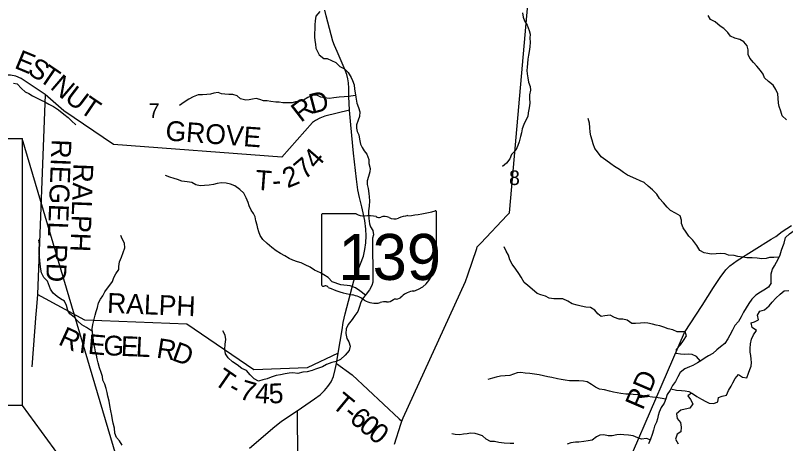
# Model space of a CAD drawing. Extents: x 0 to 34, y 0 to 22.
# Drawn here: x 4.921 to 7.127, y 17.503 to 18.731 of the extents above; entities that cross this region are included whole.
import ezdxf

# ---------------------------------------------------------------- set-up
doc = ezdxf.new("R2010")
doc.units = 0
for name, color, linetype in [('GM_X_County_Road', 7, 'Continuous'), ('GM_X_County_Road_Text', 7, 'Continuous'), ('GM_X_Minor_River', 7, 'Continuous'), ('GM_X_Section_Text', 7, 'Continuous'), ('GM_X_State_Location', 7, 'Continuous'), ('GM_X_State_Route', 7, 'Continuous'), ('GM_X_State_Shield', 7, 'Continuous'), ('GM_X_Township_Road', 7, 'Continuous'), ('GM_X_Township_Road_Text', 7, 'Continuous'), ('SH_Text', 7, 'Continuous')]:
    doc.layers.add(name, color=color, linetype=linetype)

msp = doc.modelspace()

# ---------------------------------------------------------------- linework, layer by layer
at = {"layer": 'GM_X_County_Road'}
msp.add_lwpolyline([(6.5942, 17.2578), (6.8375, 17.8217), (6.888, 17.8994), (6.9203, 17.9509), (6.9396, 17.9796), (6.9563, 18.001), (6.9677, 18.0129), (6.9885, 18.0281), (7.086, 18.0898), (7.0991, 18.0972), (7.1177, 18.1111), (7.1444, 18.1289)], dxfattribs=at)
at = {"layer": 'GM_X_Minor_River'}
for points in [[(5.7926, 18.7415), (5.7815, 18.7283), (5.7795, 18.7146), (5.7791, 18.7033), (5.779, 18.6904), (5.7781, 18.6805), (5.7781, 18.6691), (5.7791, 18.6585), (5.7802, 18.6486), (5.782, 18.6369), (5.7861, 18.6274), (5.791, 18.6178), (5.8041, 18.6071)], [(6.3738, 18.7376), (6.3756, 18.7258), (6.3789, 18.7152), (6.3868, 18.703), (6.3927, 18.6874), (6.3953, 18.6764), (6.3948, 18.665), (6.3959, 18.654), (6.395, 18.6407), (6.3927, 18.6267), (6.3911, 18.6169), (6.3891, 18.6055), (6.3875, 18.5926), (6.3867, 18.5824), (6.3855, 18.5729), (6.3866, 18.5634), (6.3891, 18.5513), (6.3906, 18.5391), (6.3954, 18.5266), (6.3965, 18.5163), (6.3937, 18.5027), (6.394, 18.4932), (6.3943, 18.4792), (6.3923, 18.4655), (6.39, 18.4511), (6.3884, 18.4409), (6.383, 18.4307), (6.3776, 18.4175), (6.373, 18.4057), (6.3703, 18.3936), (6.3679, 18.3834), (6.3637, 18.3686), (6.3602, 18.3576), (6.3541, 18.3448), (6.3422, 18.332), (6.3376, 18.3199), (6.3277, 18.3074), (6.3167, 18.298)], [(7.1296, 18.431), (7.1176, 18.4428), (7.1135, 18.4565), (7.1087, 18.4698), (7.1065, 18.4793), (7.1062, 18.4937), (7.1048, 18.5055), (7.0992, 18.5181), (7.0913, 18.531), (7.0785, 18.541), (7.0669, 18.5513), (7.0631, 18.5619), (7.0553, 18.573), (7.0448, 18.5852), (7.035, 18.5959), (7.0249, 18.6077), (7.0204, 18.6183), (7.0197, 18.6324), (7.0168, 18.643), (7.0074, 18.6552), (6.9961, 18.6614), (6.9821, 18.6649), (6.9697, 18.6714), (6.9618, 18.6817), (6.9498, 18.6928), (6.9396, 18.7), (6.9257, 18.7119), (6.9125, 18.7184), (6.9054, 18.7306)], [(5.8041, 18.6071), (5.814, 18.6067), (5.8264, 18.6013), (5.8392, 18.5959), (5.8505, 18.5841), (5.8633, 18.5772), (5.8746, 18.5665), (5.8829, 18.5531), (5.8866, 18.5436), (5.891, 18.5318), (5.8928, 18.5189), (5.8947, 18.5087), (5.8965, 18.4961), (5.899, 18.4794), (5.9035, 18.4665), (5.9072, 18.4544), (5.9063, 18.4411), (5.9032, 18.4301), (5.8978, 18.4173), (5.8978, 18.4074), (5.9, 18.3979), (5.9044, 18.3884), (5.9062, 18.3759), (5.9099, 18.3618), (5.914, 18.3519), (5.9204, 18.3424), (5.9279, 18.3325), (5.9331, 18.318), (5.9338, 18.3059), (5.9371, 18.2918), (5.9366, 18.2824), (5.9324, 18.2691), (5.9285, 18.2566), (5.9288, 18.2464), (5.9314, 18.235), (5.9332, 18.2202), (5.9346, 18.2107), (5.9353, 18.1989), (5.9344, 18.1838), (5.9325, 18.1705), (5.9324, 18.1603), (5.9335, 18.1485), (5.9349, 18.1337), (5.9382, 18.1242), (5.9449, 18.1139), (5.9468, 18.1021), (5.944, 18.0923), (5.944, 18.0805), (5.9435, 18.0711), (5.9435, 18.0616), (5.9437, 18.0479), (5.944, 18.0377), (5.9451, 18.0252), (5.9449, 17.999), (5.9445, 17.988), (5.9447, 17.9665)], [(4.9152, 18.5365), (4.9258, 18.5345), (4.9389, 18.5215), (4.9494, 18.5112), (4.9596, 18.507), (4.9702, 18.5004), (4.9811, 18.4939), (4.9947, 18.4874), (5.0056, 18.4828), (5.0166, 18.4766), (5.0301, 18.4693), (5.0448, 18.4601), (5.0599, 18.4471), (5.0723, 18.4376), (5.0817, 18.428), (5.0941, 18.4169)], [(5.8958, 18.5011), (5.8738, 18.4986), (5.8628, 18.4971), (5.8488, 18.4961), (5.8329, 18.4939), (5.8211, 18.4925), (5.8068, 18.4941), (5.7962, 18.4964), (5.7845, 18.5018), (5.772, 18.5015), (5.7587, 18.4952), (5.7462, 18.4873), (5.734, 18.484), (5.7234, 18.4825), (5.714, 18.4803), (5.7022, 18.4804), (5.6871, 18.4805), (5.6769, 18.4824), (5.6671, 18.4821), (5.6523, 18.4837), (5.6425, 18.4853), (5.6319, 18.4858), (5.6209, 18.49), (5.6104, 18.492), (5.6005, 18.4905), (5.5907, 18.4887), (5.5808, 18.4873), (5.5661, 18.4912), (5.5563, 18.5003), (5.5442, 18.5042), (5.5321, 18.5043), (5.5212, 18.5047), (5.5113, 18.5059), (5.5015, 18.5094), (5.4898, 18.5076), (5.4799, 18.505), (5.4697, 18.5039), (5.4572, 18.5029), (5.4443, 18.5026), (5.4303, 18.497), (5.4181, 18.491), (5.4044, 18.4816), (5.3915, 18.4726)], [(7.109, 18.0378), (7.0936, 18.0368), (7.0811, 18.0365), (7.0717, 18.0343), (7.0595, 18.0329), (7.0459, 18.0349), (7.0316, 18.0357), (7.0164, 18.0358), (7.0047, 18.0382), (6.99, 18.0398), (6.9794, 18.0421), (6.9635, 18.0434), (6.9537, 18.0469), (6.9404, 18.0481), (6.928, 18.0474), (6.9143, 18.0464), (6.9041, 18.0483), (6.8943, 18.0503), (6.8815, 18.0572), (6.8733, 18.0713), (6.8612, 18.0862), (6.8496, 18.098), (6.8421, 18.109), (6.8335, 18.1216), (6.8286, 18.1338), (6.8287, 18.144), (6.825, 18.1558), (6.8118, 18.1639), (6.7979, 18.1715), (6.7877, 18.1807), (6.7772, 18.1937), (6.7659, 18.2055), (6.7585, 18.2181), (6.7464, 18.2307), (6.7336, 18.241), (6.7216, 18.2513), (6.7107, 18.2567), (6.6986, 18.2621), (6.6748, 18.2725), (6.6624, 18.2805), (6.6511, 18.2893), (6.6375, 18.2978), (6.6262, 18.305), (6.6127, 18.3158), (6.5991, 18.3257), (6.5883, 18.3398), (6.5811, 18.3493), (6.5759, 18.3623), (6.573, 18.3733), (6.5693, 18.3855), (6.5671, 18.3961), (6.566, 18.409), (6.5654, 18.4219), (6.562, 18.4356)], [(5.8285, 17.9667), (5.8169, 17.979), (5.8045, 17.987), (5.7947, 17.9932), (5.7781, 18.0005), (5.7649, 18.0093), (5.7509, 18.0158), (5.7396, 18.0212), (5.7294, 18.0243), (5.7154, 18.0293), (5.7053, 18.034), (5.6932, 18.0413), (5.6804, 18.0485), (5.6679, 18.0558), (5.6551, 18.065), (5.6424, 18.0769), (5.6299, 18.0883), (5.6217, 18.1001), (5.6187, 18.1104), (5.6158, 18.1203), (5.6136, 18.1298), (5.6099, 18.1416), (5.6077, 18.153), (5.6028, 18.1625), (5.5961, 18.172), (5.5905, 18.1845), (5.5879, 18.1944), (5.5819, 18.2081), (5.5756, 18.2207), (5.5636, 18.2318), (5.5496, 18.2421), (5.5376, 18.2471), (5.5251, 18.2498), (5.5115, 18.2503), (5.4994, 18.2489), (5.4887, 18.2459), (5.4759, 18.2437), (5.4622, 18.2434), (5.4501, 18.2424), (5.438, 18.2455), (5.426, 18.2516), (5.4131, 18.254), (5.398, 18.2552), (5.3855, 18.2606), (5.3757, 18.2634), (5.3636, 18.2672), (5.3508, 18.2722)], [(7.0856, 17.9641), (7.0857, 17.9796), (7.0854, 17.9898), (7.0892, 18.0031), (7.095, 18.0129), (7.1015, 18.0235), (7.1072, 18.0337), (7.1118, 18.0447), (7.1153, 18.0579), (7.1192, 18.0685), (7.123, 18.0783), (7.1273, 18.0939), (7.1387, 18.1048), (7.152, 18.1138), (7.1638, 18.1198), (7.1767, 18.1227), (7.1873, 18.1177), (7.2005, 18.118), (7.2127, 18.1244), (7.2256, 18.1311), (7.2358, 18.1341), (7.2498, 18.1371)], [(5.1993, 17.9681), (5.2027, 17.9797), (5.2089, 17.9895), (5.2173, 18.002), (5.2173, 18.0114), (5.2193, 18.0239), (5.2247, 18.0379), (5.2297, 18.0512), (5.234, 18.0648), (5.2333, 18.0777), (5.227, 18.0903), (5.2229, 18.1001)], [(5.0134, 17.9691), (5.0028, 17.979), (4.9957, 17.993), (4.9935, 18.0037), (4.992, 18.0177), (4.9913, 18.0283), (4.9891, 18.0488), (4.9895, 18.062), (4.9896, 18.0753), (4.9885, 18.0878)], [(6.3787, 17.9656), (6.3697, 17.9806), (6.3626, 17.9909), (6.3544, 18.0038), (6.3435, 18.0179), (6.3372, 18.0305), (6.3338, 18.0434), (6.3271, 18.0552), (6.3211, 18.0674)], [(5.1419, 17.8248), (5.1245, 17.8364), (5.1117, 17.844), (5.0996, 17.8543), (5.089, 17.8657), (5.077, 17.8752), (5.0709, 17.8851), (5.0676, 17.8991), (5.0612, 17.9113), (5.0506, 17.9181), (5.0408, 17.925), (5.0295, 17.9349), (5.022, 17.9463), (5.0134, 17.9691)], [(5.2051, 17.548), (5.2014, 17.5616), (5.1992, 17.5719), (5.1973, 17.5836), (5.1943, 17.5977), (5.1918, 17.6125), (5.1895, 17.6254), (5.1862, 17.639), (5.1839, 17.6496), (5.1813, 17.6618), (5.1776, 17.6739), (5.1716, 17.6849), (5.1705, 17.6956), (5.1664, 17.7073), (5.1619, 17.7206), (5.1582, 17.7346), (5.1556, 17.7468), (5.1529, 17.757), (5.1507, 17.7665), (5.1481, 17.7775), (5.1459, 17.7885), (5.1448, 17.7988), (5.1441, 17.8082), (5.1422, 17.8215), (5.1411, 17.8321), (5.1427, 17.845), (5.1457, 17.8564), (5.1492, 17.8711), (5.1527, 17.8825), (5.1557, 17.8939), (5.1595, 17.9067), (5.1645, 17.917), (5.171, 17.9268), (5.1771, 17.9385), (5.1993, 17.9681)], [(5.9447, 17.9665), (5.9421, 17.9561), (5.9356, 17.9443), (5.9253, 17.9315), (5.9151, 17.9183), (5.9097, 17.9061), (5.907, 17.8959), (5.9021, 17.8823), (5.8937, 17.8709), (5.8853, 17.8592), (5.8739, 17.8449), (5.8686, 17.832), (5.8678, 17.8187), (5.8708, 17.8051), (5.876, 17.7952), (5.8801, 17.7823), (5.8767, 17.7706), (5.8653, 17.757), (5.8524, 17.7449), (5.8395, 17.7392), (5.827, 17.7355), (5.8126, 17.7299), (5.8005, 17.7231), (5.7808, 17.7163), (5.7709, 17.7133), (5.7565, 17.7092), (5.7444, 17.7078), (5.73, 17.7048), (5.716, 17.7064), (5.7051, 17.7053), (5.6937, 17.703), (5.6801, 17.7004), (5.668, 17.6982), (5.654, 17.6941), (5.6418, 17.6888), (5.6301, 17.6858), (5.6172, 17.6825), (5.6048, 17.6893), (5.5938, 17.7008), (5.5825, 17.7129), (5.5697, 17.7187), (5.5561, 17.729), (5.5429, 17.7381), (5.5305, 17.7488), (5.5226, 17.7605), (5.5207, 17.7734), (5.5223, 17.7882), (5.5242, 17.8019), (5.5216, 17.814), (5.5149, 17.8265)], [(5.9235, 17.9291), (5.908, 17.9414), (5.8948, 17.9498), (5.8796, 17.9552), (5.8531, 17.9588), (5.8285, 17.9667)], [(6.8831, 17.74), (6.8719, 17.7527), (6.8599, 17.7588), (6.8477, 17.7596), (6.8368, 17.7589), (6.8266, 17.7593), (6.8137, 17.7613), (6.8149, 17.7745), (6.8259, 17.7866), (6.8343, 17.7991), (6.843, 17.8123), (6.8397, 17.8241), (6.817, 17.8242), (6.8041, 17.8295), (6.7909, 17.8326), (6.7788, 17.8372), (6.7671, 17.8414), (6.7565, 17.843), (6.7463, 17.8453), (6.7323, 17.8484), (6.7217, 17.8492), (6.7111, 17.8489), (6.6975, 17.8478), (6.6865, 17.8474), (6.673, 17.8573), (6.6605, 17.8604), (6.6503, 17.8601), (6.6374, 17.8651), (6.625, 17.8719), (6.6098, 17.8693), (6.5992, 17.8679), (6.5894, 17.8755), (6.5811, 17.8861), (6.5679, 17.8938), (6.5547, 17.8949), (6.5415, 17.8977), (6.5297, 17.9), (6.5161, 17.9038), (6.5037, 17.9118), (6.4889, 17.9179), (6.4787, 17.9187), (6.4636, 17.9188), (6.45, 17.9207), (6.4394, 17.9257), (6.4258, 17.9296), (6.4156, 17.9334), (6.4013, 17.946), (6.3888, 17.957), (6.3787, 17.9656)], [(7.0856, 17.9641), (7.0781, 17.9521), (7.0644, 17.9434), (7.055, 17.9374), (7.0417, 17.9291), (7.0307, 17.9178), (7.0219, 17.9053), (7.0143, 17.8928), (7.0067, 17.8799), (6.9995, 17.8671), (6.9926, 17.8538), (6.9816, 17.8418), (6.9755, 17.8281), (6.9671, 17.8145), (6.9618, 17.8035), (6.9527, 17.7903), (6.9405, 17.7805), (6.9306, 17.7726), (6.9189, 17.762), (6.9067, 17.7552), (6.8969, 17.7488), (6.884, 17.7405), (6.8745, 17.7349), (6.8612, 17.7274), (6.8518, 17.7236), (6.8389, 17.7176), (6.8256, 17.7074), (6.8184, 17.6949), (6.8119, 17.6817), (6.8032, 17.6696), (6.7963, 17.6567), (6.7883, 17.6446), (6.7837, 17.6314), (6.7791, 17.6196), (6.7711, 17.6068), (6.7654, 17.5935), (6.762, 17.5837), (6.7604, 17.5742), (6.757, 17.5644), (6.752, 17.5538), (6.749, 17.542), (6.7448, 17.5299), (6.7398, 17.5159), (6.7341, 17.5027)], [(6.7984, 17.6607), (6.8148, 17.6567), (6.8292, 17.6558), (6.8398, 17.655), (6.8504, 17.6523), (6.8602, 17.647), (6.8727, 17.6386), (6.8859, 17.6306), (6.8987, 17.6237), (6.9085, 17.6195), (6.9214, 17.6183), (6.9331, 17.6228), (6.9351, 17.6357), (6.9453, 17.6391), (6.9582, 17.6421), (6.9639, 17.6553), (6.9711, 17.6682), (6.9761, 17.678), (6.9829, 17.6901), (6.992, 17.7015), (7.0034, 17.6942), (7.0162, 17.6923), (7.0208, 17.7055), (7.025, 17.7154), (7.0285, 17.7256), (7.0292, 17.7354), (7.0285, 17.7453), (7.0274, 17.7555), (7.026, 17.7654), (7.026, 17.7764), (7.0264, 17.7893), (7.0291, 17.8025), (7.0356, 17.815), (7.0436, 17.8275), (7.0315, 17.8366), (7.0289, 17.8492), (7.0384, 17.8525), (7.0497, 17.8578), (7.0464, 17.8715), (7.0532, 17.8832), (7.0665, 17.8865), (7.0805, 17.8986), (7.0889, 17.9088), (7.0992, 17.9205), (7.1121, 17.9315), (7.1231, 17.9409), (7.1363, 17.9424)], [(6.7837, 17.6312), (6.7682, 17.6341), (6.7565, 17.636), (6.7459, 17.6364), (6.7319, 17.638), (6.7194, 17.6407), (6.7058, 17.643), (6.6907, 17.6446), (6.6805, 17.6454), (6.6699, 17.6451), (6.6552, 17.647), (6.6446, 17.6493), (6.6347, 17.6509), (6.6223, 17.654), (6.6087, 17.6571), (6.5943, 17.6598), (6.5826, 17.6655), (6.5709, 17.6728), (6.5588, 17.6808), (6.5486, 17.6819), (6.535, 17.6831), (6.5217, 17.6832), (6.5085, 17.6836), (6.496, 17.6852), (6.4843, 17.6875), (6.4741, 17.689), (6.4575, 17.6925), (6.4461, 17.6948), (6.4337, 17.6979), (6.4216, 17.7006), (6.4083, 17.7029), (6.3947, 17.7045), (6.3815, 17.7057), (6.3686, 17.7069), (6.3584, 17.7058), (6.3478, 17.7028), (6.3376, 17.6987), (6.3236, 17.6976), (6.3103, 17.6969), (6.2982, 17.6943), (6.2872, 17.6909), (6.274, 17.6872)], [(6.858, 17.6482), (6.8469, 17.6406), (6.8548, 17.6296), (6.8612, 17.6174), (6.8525, 17.6053), (6.8396, 17.602), (6.8267, 17.599), (6.8146, 17.5884), (6.8164, 17.5755), (6.8262, 17.5641), (6.8281, 17.5508), (6.8273, 17.5372), (6.8166, 17.53), (6.8117, 17.5164), (6.8199, 17.5031)], [(5.2265, 17.4986), (5.2194, 17.5111), (5.2103, 17.521), (5.2062, 17.5336), (5.2051, 17.548)], [(6.349, 17.5034), (6.3387, 17.5038), (6.3206, 17.505), (6.3062, 17.5066), (6.2937, 17.5093), (6.2816, 17.5097), (6.2692, 17.5158), (6.259, 17.5254), (6.248, 17.5292), (6.2378, 17.5323), (6.2246, 17.5331), (6.2148, 17.5316), (6.2042, 17.5305), (6.1943, 17.5283), (6.1807, 17.5298), (6.1709, 17.5314)], [(6.7389, 17.5139), (6.7285, 17.5179), (6.7144, 17.516), (6.7042, 17.5202), (6.691, 17.526), (6.6774, 17.5275), (6.6642, 17.5287), (6.6532, 17.5299), (6.6434, 17.5284), (6.6301, 17.5254), (6.6188, 17.5259), (6.6067, 17.5286), (6.5953, 17.5279), (6.5855, 17.5233), (6.573, 17.5135), (6.5612, 17.5109), (6.5491, 17.5098), (6.5347, 17.5076), (6.5249, 17.5073), (6.5124, 17.5054), (6.5018, 17.5021)]]:
    msp.add_lwpolyline(points, dxfattribs=at)
at = {"layer": 'GM_X_State_Route'}
msp.add_lwpolyline([(5.592, 17.4906), (5.6638, 17.5521), (5.6826, 17.5672), (5.6974, 17.5776), (5.7281, 17.597), (5.7781, 17.6315), (5.7939, 17.6435), (5.8065, 17.6554), (5.816, 17.6668), (5.8251, 17.6802), (5.832, 17.6958), (5.8371, 17.7157), (5.8407, 17.7333), (5.8453, 17.7626), (5.8567, 17.8295), (5.8601, 17.8507), (5.8654, 17.875), (5.8902, 17.9696), (5.9177, 18.0407), (5.9224, 18.0596), (5.9252, 18.079), (5.9254, 18.0988), (5.9247, 18.1177), (5.9218, 18.1428), (5.9129, 18.1816), (5.9063, 18.2088), (5.902, 18.2305), (5.8978, 18.261), (5.8899, 18.3362), (5.8823, 18.4166), (5.8782, 18.4588), (5.8761, 18.4982), (5.8761, 18.5224), (5.8751, 18.5372), (5.8736, 18.5485), (5.8703, 18.561), (5.8659, 18.5736), (5.8424, 18.6276), (5.835, 18.644), (5.8307, 18.6568), (5.8109, 18.7289), (5.8078, 18.7458)], dxfattribs=at)
at = {"layer": 'GM_X_State_Shield'}
for p, q in [((5.7977, 18.1585), (5.7977, 17.9584)), ((5.8975, 18.162), (5.801, 18.162)), ((6.1273, 18.0623), (6.1273, 18.1669)), ((6.1273, 18.0623), (6.1273, 18.0623))]:
    msp.add_line(p, q, dxfattribs=at)
for centre, major_axis, start_param, end_param in [((5.8015, 18.159), (0.00382, 0), 1.712693, 3.28349), ((5.9205, 18.1852), (0.037, 0), 4.042523, 4.731795), ((6.0099, 18.4348), (0.3495, 0), 4.814394, 5.042369), ((6.1237, 18.1674), (0.00367, 0), 6.141152, 7.989035), ((5.9328, 18.0496), (0.133, 0), 1.404758, 1.657858), ((5.9629, 18.16), (0.0107, 0), 3.836095, 5.185415), ((5.9786, 18.1369), (0.0222, 0), 0.950623, 2.079405), ((6.0073, 18.1686), (0.0267, 0), 4.081561, 5.145723), ((6.0545, 18.1009), (0.0703, 0), 1.699011, 2.107814), ((6.1265, 18.0546), (0.00568, 0), 1.883978, 3.671073), ((6.0903, 18.0413), (0.0341, 0), 5.934695, 6.695948), ((6.1234, 18.0619), (0.00393, 0), 5.05454, 6.418171), ((6.1405, 18.0184), (0.0248, 0), 2.387724, 3.262537), ((6.0295, 18.0051), (0.0874, 0), 5.101752, 6.440018), ((5.8015, 17.958), (0.00385, 0), 3.00124, 4.508301), ((5.8021, 17.9785), (0.0294, 0), 4.665946, 4.897461), ((5.8081, 17.9469), (0.0106, 0), 0.519207, 1.627899), ((5.942, 18.1267), (0.2524, 0), 4.195997, 4.488961), ((6.0664, 17.9022), (0.0479, 0), 1.647645, 2.488434), ((5.8667, 17.8685), (0.079, 0), 0.823519, 1.323587), ((5.9521, 17.9459), (0.0501, 0), 4.026481, 4.996735), ((5.9847, 17.9309), (0.0267, 0), 4.691044, 5.507374), ((6.0089, 17.9115), (0.00752, 0), 1.147584, 2.315152), ((6.0057, 17.939), (0.0282, 0), 4.937069, 5.64225), ((5.9811, 17.8767), (0.0412, 0), 1.495662, 1.94098)]:
    msp.add_ellipse(centre, major_axis=major_axis, ratio=0.8, start_param=start_param, end_param=end_param, dxfattribs=at)
at = {"layer": 'GM_X_Township_Road'}
msp.add_line((4.98, 17.8749), (4.9683, 17.7232), dxfattribs=at)
for points in [[(6.0069, 17.5018), (6.0249, 17.5587), (6.0279, 17.5682), (6.032, 17.5773), (6.2101, 17.9682), (6.2166, 17.987), (6.2425, 18.0626), (6.244, 18.067), (6.2545, 18.0781), (6.3298, 18.1581), (6.3363, 18.165), (6.3373, 18.1755), (6.3996, 18.8819)], [(5.8782, 18.4588), (5.8073, 18.4419), (5.7932, 18.4365), (5.7802, 18.4292), (5.7723, 18.4238), (5.6842, 18.3245), (5.2023, 18.3605), (5.0598, 18.4567), (5.0058, 18.5041), (4.9373, 18.5493), (4.9227, 18.5564), (4.9074, 18.5594), (4.8834, 18.5594), (4.8595, 18.5579)], [(5.0058, 18.5041), (4.9843, 17.9305), (4.9807, 17.8836), (4.98, 17.8749)], [(5.8453, 17.7626), (5.7565, 17.7203), (5.6039, 17.7153), (5.4123, 17.846), (5.1196, 17.8574), (4.9843, 17.9305)], [(5.8407, 17.7333), (5.8854, 17.7003), (6.0203, 17.5745), (6.0279, 17.5682)], [(5.7281, 17.597), (5.7288, 17.4586), (5.7081, 17.3077), (5.7076, 17.0179), (5.7121, 16.7986), (5.7057, 16.5833), (5.702, 16.3168)]]:
    msp.add_lwpolyline(points, dxfattribs=at)
at = {"layer": 'SH_Text'}
for points in [[(3.1565, 18.3776), (4.9408, 18.3776), (4.9408, 17.6129), (3.1565, 17.6129)], [(5.3209, 17.091), (4.9408, 18.3776), (4.9408, 17.6129)]]:
    msp.add_lwpolyline(points, close=True, dxfattribs=at)

# ---------------------------------------------------------------- texts
at = {"layer": 'GM_X_County_Road_Text'}
msp.add_text('RD', height=0.05682, rotation=66.7366, dxfattribs=at).set_placement((6.7179, 17.5972))
at = {"layer": 'GM_X_Section_Text'}
for s, p in [('7', (5.3028, 18.4367)), ('8', (6.3349, 18.2445))]:
    msp.add_text(s, height=0.0419, rotation=0, dxfattribs=at).set_placement(p)
at = {"layer": 'GM_X_State_Location'}
msp.add_text('139', height=0.000189, rotation=0, dxfattribs=at).set_placement((5.892, 18.0314))
for s in ['s', 'r']:
    msp.add_text(s, height=0.000189, dxfattribs=at).set_placement((5.9588, 18.0452))
at = {"layer": 'GM_X_State_Shield'}
msp.add_text('139', height=0.13184, dxfattribs=at).set_placement((5.8462, 17.9725))
at = {"layer": 'GM_X_Township_Road_Text'}
for s, height, rotation, p in [('E', 0.0568, 337.5516, (4.9154, 18.5809)), ('S', 0.0568, 327.3036, (4.9523, 18.5659)), ('T', 0.0568, 325.6835, (4.9842, 18.5454)), ('N', 0.0568, 319.5564, (5.018, 18.5224)), ('U', 0.0568, 322.9198, (5.0589, 18.4877)), ('D', 0.0568, 14.6839, (5.7705, 18.448)), ('T', 0.0568, 325.8906, (5.1014, 18.4557)), ('R', 0.0568, 37.5412, (5.7388, 18.4222)), ('GROVE', 0.05682, 355.7495, (5.3495, 18.3726)), ('RIEGEL RD', 0.05682, 267.7514, (5.025, 18.3764)), ('4', 0.0568, 49.0848, (5.7827, 18.2872)), ('7', 0.0568, 40.1844, (5.7491, 18.2579)), ('RALPH', 0.05682, 267.9025, (5.0877, 18.3071)), ('2', 0.0568, 22.3835, (5.7004, 18.2346)), ('T', 0.0568, 355.6822, (5.6065, 18.2314)), ('-', 0.0568, 4.5826, (5.6585, 18.2283)), ('RALPH', 0.05682, 357.6931, (5.1829, 17.8785)), ('R', 0.0568, 335.2976, (5.041, 17.7888)), ('I', 0.0568, 352.8112, (5.1016, 17.7642)), ('E', 0.0568, 354.9951, (5.1271, 17.761)), ('G', 0.0568, 357.4761, (5.1721, 17.7571)), ('E', 0.0568, 357.7111, (5.2223, 17.7549)), ('L', 0.0568, 357.2733, (5.2647, 17.7532)), ('R', 0.0568, 351.0651, (5.323, 17.75)), ('D', 0.0568, 339.8115, (5.3662, 17.7435)), ('T', 0.0568, 325.3764, (5.486, 17.6766)), ('7', 0.0568, 343.8115, (5.5594, 17.6329)), ('4', 0.0568, 356.1016, (5.6061, 17.6208)), ('5', 0.0568, 2.2466, (5.6477, 17.6183)), ('-', 0.0568, 331.5214, (5.5266, 17.649)), ('T', 0.0568, 320.4159, (5.8242, 17.6106)), ('-', 0.0568, 320.4156, (5.8569, 17.5836)), ('6', 0.0568, 320.4145, (5.8747, 17.5689)), ('0', 0.0568, 320.4107, (5.9015, 17.5467)), ('0', 0.0568, 320.3786, (5.9282, 17.5246))]:
    msp.add_text(s, height=height, rotation=rotation, dxfattribs=at).set_placement(p)

doc.saveas('drawing.dxf')
